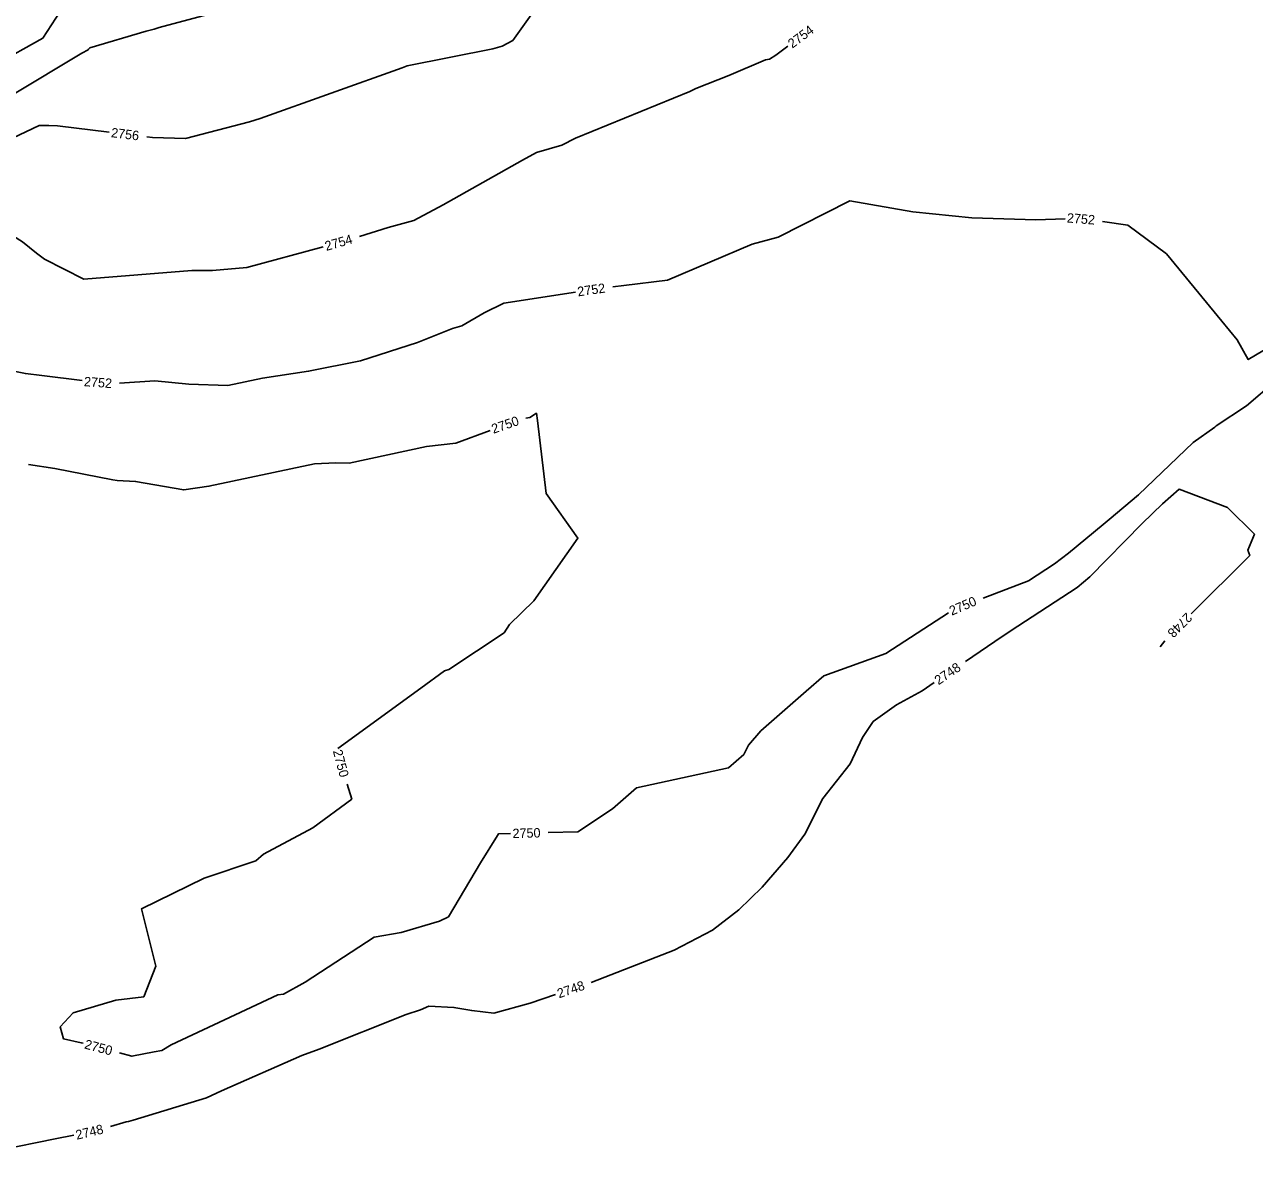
# Model space of a CAD drawing. Extents: x 1326424 to 1329294, y 1001359 to 1003823.
# Drawn here: x 1328521.7 to 1328782.8, y 1001385.6 to 1001626.3 of the extents above; entities that cross this region are included whole.
import ezdxf

# ---------------------------------------------------------------- set-up
doc = ezdxf.new("R2010")
doc.units = 0
doc.layers.add('Prop Rem of Exist Asph Pvmt', color=7, linetype='Continuous')
doc.layers.add('Scratch_Level_3', color=7, linetype='Continuous')

msp = doc.modelspace()

# ---------------------------------------------------------------- linework, layer by layer
at = {"layer": 'Prop Rem of Exist Asph Pvmt'}
msp.add_lwpolyline([(1328495.2, 1001612.73), (1328496.2, 1001612.77), (1328508.69, 1001615.6), (1328515.34, 1001617.73), (1328525.51, 1001623.41), (1328529.21, 1001629.1), (1328538.59, 1001636.25), (1328538.99, 1001636.75), (1328540.69, 1001637.36), (1328558.76, 1001642.48), (1328568.33, 1001646.35), (1328575.49, 1001648.63), (1328575.75, 1001648.74), (1328581.33, 1001651.18), (1328584.42, 1001652.93)], dxfattribs=at)
at = {"layer": 'Scratch_Level_3'}
for points in [[(1328547.59, 1001602.51), (1328548.85, 1001602.35), (1328555.84, 1001602.16), (1328569.44, 1001605.67), (1328571.7, 1001606.4), (1328601.81, 1001617.09), (1328602.88, 1001617.56), (1328621.12, 1001621.18), (1328623.05, 1001621.71), (1328625.36, 1001622.95), (1328635, 1001636.61), (1328637.23, 1001636.99)], [(1328475.98, 1001605.92), (1328476.83, 1001605.95), (1328496.63, 1001606.51), (1328499.64, 1001606.76), (1328516.85, 1001610.31), (1328519.12, 1001611.39), (1328533.82, 1001620.24), (1328535.13, 1001620.97), (1328535.23, 1001621.12), (1328535.52, 1001621.34), (1328547.46, 1001624.89), (1328549.2, 1001625.35), (1328550.21, 1001625.65), (1328571.18, 1001631.29)], [(1328592.74, 1001581.34), (1328598.85, 1001583.25), (1328604.33, 1001584.74), (1328610.57, 1001588.03), (1328627.36, 1001597.5), (1328630.33, 1001599.18), (1328635.77, 1001600.7), (1328638.61, 1001602.22), (1328662.89, 1001612.13), (1328664.22, 1001612.73), (1328671.17, 1001615.51), (1328679.01, 1001618.8), (1328679.82, 1001618.95), (1328681.17, 1001619.81), (1328683.75, 1001621.72)], [(1328441.82, 1001606.74), (1328447.16, 1001604.04), (1328450.02, 1001603.59), (1328451.67, 1001602.8), (1328462.59, 1001600.6), (1328467.1, 1001600.1), (1328471.64, 1001599.12), (1328484.13, 1001598.94), (1328493.06, 1001599.19), (1328515.22, 1001601.04), (1328517.77, 1001601.57), (1328524.73, 1001604.87), (1328526.82, 1001604.9), (1328528.65, 1001604.78), (1328539.64, 1001603.46)], [(1328445.47, 1001591.48), (1328446.88, 1001591.14), (1328462.84, 1001582.35), (1328470.97, 1001577.95), (1328482.5, 1001571.09), (1328488.02, 1001564.79), (1328496.72, 1001557.23), (1328504.94, 1001555.26), (1328514.11, 1001553.77), (1328521.84, 1001552.23), (1328525.35, 1001551.81), (1328533.89, 1001550.78)], [(1328490.24, 1001588.33), (1328492.63, 1001587.02), (1328506.73, 1001586.94), (1328510.81, 1001586.67), (1328521.18, 1001580.16), (1328524.16, 1001577.81), (1328525.87, 1001576.49), (1328534.22, 1001572.25), (1328557.15, 1001574.14), (1328561.56, 1001574.14), (1328568.88, 1001574.75), (1328585.05, 1001579.15)], [(1328646.56, 1001570.62), (1328648.93, 1001570.92), (1328658.15, 1001572.07), (1328676.13, 1001579.73), (1328681.7, 1001581.15), (1328696.87, 1001588.87), (1328710.31, 1001586.56), (1328722.81, 1001585.26), (1328736.39, 1001584.89), (1328742.61, 1001585.1)], [(1328750.56, 1001584.48), (1328755.91, 1001583.74), (1328764.13, 1001577.63), (1328775.9, 1001563.33), (1328779.13, 1001559.4), (1328781.51, 1001555.19), (1328787.33, 1001558.67), (1328790.64, 1001566.87), (1328789.98, 1001567.68), (1328790.77, 1001568.62), (1328792.81, 1001568.58), (1328797.74, 1001565.09), (1328811.08, 1001574.32), (1328812.14, 1001574.85), (1328812.49, 1001575.25), (1328813.22, 1001576.2), (1328821.04, 1001583.65)], [(1328541.84, 1001550.19), (1328549.3, 1001550.69), (1328556.56, 1001549.99), (1328564.79, 1001549.71), (1328572.21, 1001551.27), (1328581.98, 1001552.72), (1328592.99, 1001554.95), (1328605.07, 1001558.84), (1328612.52, 1001561.81), (1328614.5, 1001562.35), (1328619.27, 1001565.09), (1328623.4, 1001567.16), (1328638.65, 1001569.49)], [(1328725.18, 1001504.57), (1328734.81, 1001508.23), (1328740.35, 1001511.85), (1328743.34, 1001514.11), (1328750.69, 1001520.2), (1328751.95, 1001521.26), (1328758.22, 1001526.48), (1328769.78, 1001537.61), (1328774.4, 1001540.88), (1328774.69, 1001541.15), (1328781.16, 1001545.4), (1328787.46, 1001550.78), (1328791.45, 1001553.88), (1328797.3, 1001559.81), (1328804.26, 1001564.63)], [(1328628.08, 1001542.74), (1328628.93, 1001542.9), (1328630.34, 1001543.8), (1328630.55, 1001542.24), (1328632.41, 1001526.77), (1328639.15, 1001517.31), (1328629.76, 1001503.97), (1328624.61, 1001498.99), (1328623.49, 1001497.17), (1328611.71, 1001489.4), (1328610.85, 1001489.14), (1328605.81, 1001485.47), (1328588.15, 1001472.63)], [(1328522.48, 1001532.95), (1328528.1, 1001532.06), (1328540.4, 1001529.64), (1328541.29, 1001529.54), (1328545.23, 1001529.35), (1328555.46, 1001527.52), (1328560.79, 1001528.31), (1328583.19, 1001533.05), (1328587.73, 1001533.29), (1328590.56, 1001533.18), (1328606.99, 1001536.74), (1328613.2, 1001537.43), (1328620.53, 1001540.16)], [(1328721.45, 1001491.12), (1328727.7, 1001495.34), (1328730.96, 1001497.52), (1328745.16, 1001506.83), (1328747.88, 1001509.07), (1328758.97, 1001520.38), (1328763.32, 1001524.56), (1328766.83, 1001527.7), (1328777.07, 1001523.83), (1328782.81, 1001518.17), (1328781.43, 1001514.78), (1328781.81, 1001513.62), (1328769.39, 1001501.2)], [(1328632.84, 1001454.82), (1328639.12, 1001454.99), (1328646.48, 1001459.81), (1328651.61, 1001464.29), (1328671.11, 1001468.54), (1328674.36, 1001471.35), (1328675.35, 1001473.33), (1328678.03, 1001476.41), (1328687.61, 1001484.79), (1328691.41, 1001488.07), (1328704.53, 1001492.84), (1328717.86, 1001501.42)], [(1328763.76, 1001495.52), (1328762.8, 1001494.2)], [(1328642, 1001423.01), (1328650.29, 1001426.25), (1328659.57, 1001429.81), (1328667.76, 1001434.07), (1328673.33, 1001438.41), (1328678.26, 1001443.2), (1328683.71, 1001449.54), (1328687.36, 1001454.48), (1328691.14, 1001462.03), (1328697, 1001469.42), (1328699.61, 1001474.99), (1328701.84, 1001478.35), (1328706.84, 1001481.94), (1328712.24, 1001484.9), (1328714.82, 1001486.64)], [(1328590.16, 1001465.09), (1328591.13, 1001461.91), (1328582.88, 1001455.78), (1328572.38, 1001450.25), (1328570.74, 1001448.84), (1328559.77, 1001445.13), (1328546.46, 1001438.6), (1328549.53, 1001426.45), (1328546.97, 1001419.94), (1328541.03, 1001419.25), (1328531.97, 1001416.53), (1328529.19, 1001413.59), (1328529.93, 1001411), (1328533.7, 1001410.18), (1328534.09, 1001410.07)], [(1328541.82, 1001408.02), (1328544.43, 1001407.33), (1328549.19, 1001408.27), (1328550.8, 1001408.56), (1328552.75, 1001409.74), (1328575.43, 1001420.35), (1328576.65, 1001420.52), (1328581.22, 1001423.08), (1328595.86, 1001432.58), (1328601.62, 1001433.61), (1328609.79, 1001435.98), (1328611.67, 1001436.94), (1328618.48, 1001448.35), (1328622.11, 1001454.21), (1328622.32, 1001454.54), (1328624.84, 1001454.61)], [(1328539.88, 1001392.44), (1328543.22, 1001393.43), (1328543.71, 1001393.51), (1328544.68, 1001393.75), (1328560.29, 1001398.51), (1328563.49, 1001399.96), (1328580.53, 1001407.49), (1328584.18, 1001408.83), (1328602.69, 1001416.19), (1328605.71, 1001417.21), (1328607.49, 1001417.97), (1328612.84, 1001417.7), (1328616.62, 1001417.02), (1328621.31, 1001416.47), (1328629.04, 1001418.63), (1328634.43, 1001420.44)], [(1328434.17, 1001397.71), (1328450.99, 1001392.82), (1328453.09, 1001392.75), (1328464.86, 1001391.55), (1328469.66, 1001390.73), (1328470.35, 1001390.53), (1328484.54, 1001387.87), (1328491.77, 1001385.65), (1328497.43, 1001385.79), (1328504.6, 1001387.71), (1328511.29, 1001386.98), (1328516.27, 1001387.37), (1328528.16, 1001389.83), (1328532.1, 1001390.61)]]:
    msp.add_lwpolyline(points, dxfattribs=at)

# ---------------------------------------------------------------- texts
for s, rotation, p in [('2754', 36.5333, (1328684.68, 1001621.17)), ('2756', 353.1422, (1328539.94, 1001602.42)), ('2752', 355.5098, (1328742.94, 1001584.31)), ('2754', 15.9593, (1328585.74, 1001578.25)), ('2752', 8.1329, (1328639.19, 1001568.6)), ('2752', 355.7444, (1328534.21, 1001549.57)), ('2750', 18.8704, (1328621.21, 1001539.45)), ('2750', 23.2751, (1328718.54, 1001500.82)), ('2748', 225.2901, (1328768.37, 1001501.62)), ('2748', 34.0407, (1328715.73, 1001486.05)), ('2750', 284.9325, (1328587.1, 1001472.12)), ('2750', 1.525, (1328625.29, 1001453.62)), ('2748', 18.7389, (1328635.15, 1001419.62)), ('2750', 345.1318, (1328534.23, 1001409)), ('2748', 13.2593, (1328532.76, 1001389.6))]:
    msp.add_text(s, height=2, rotation=rotation, dxfattribs=at).set_placement(p)

doc.saveas('drawing.dxf')
